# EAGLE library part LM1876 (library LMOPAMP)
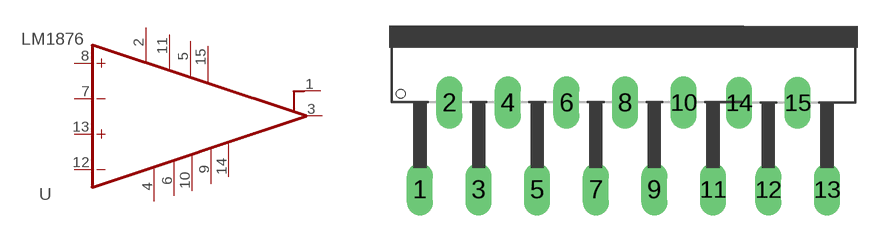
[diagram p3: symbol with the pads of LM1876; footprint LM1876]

Designator prefix -

## LM1876  [LM1876]
1  OUTB  out
2  V+  pwr
3  OUTA  out
4  V-  pwr
5  GNDA  pwr
6  MUTEA  pwr
7  -INA  in
8  +INA  in
9  STANDBAYA  pwr
10  GNDB  pwr
11  MUTEB  pwr
12  -INB  in
13  +INB  in
14  STANDBAYB  pwr
15  V+2  pwr

## Footprint LM1876 (pad centres in mm)
drill 1.016 long: 1 -11.049,-1.905; 2 -9.347,3.15; 3 -7.645,-1.905; 4 -5.944,3.15; 5 -4.242,-1.905; 6 -2.54,3.15; 7 -0.838,-1.905; 8 0.864,3.15; 9 2.565,-1.905; 10 4.267,3.15; 11 5.969,-1.905; 12 9.185,-1.915; 13 12.589,-1.915; 14 7.484,3.14; 15 10.887,3.14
